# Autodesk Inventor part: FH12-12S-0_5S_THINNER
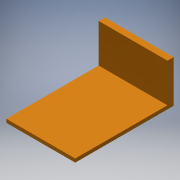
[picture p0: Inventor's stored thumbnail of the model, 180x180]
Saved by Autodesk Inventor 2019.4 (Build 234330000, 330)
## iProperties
Created: 2019-11
Part Number: FH12-12S-0_5S_THINNER
Material: Generic
Document SubType Name: Modeling
Designer: Willist
Density: 1 g/cm^3
Appearance: FH12-12S-0_5SH_THINER, FH12-12S-0_5S_THINNER
Author: Willist
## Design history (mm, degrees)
sketch "FH12-12S-0_5SH_THINER, FH12-12S-0_5S_THINNER_19"
  geometry: L1 (-5.6, 3.95)-(5.6, 3.95); L2 (5.6, 3.95)-(5.6, -2.9); L3 (5.6, -2.9)-(-5.6, -2.9); L4 (-5.6, -2.9)-(-5.6, 3.95)
  constraints: 8 end point
extrude "Extrusion1" join sketch "FH12-12S-0_5SH_THINER, FH12-12S-0_5S_THINNER_19" distance "d0" = 1; taper "d1" = 0 deg
sketch "Sketch2"
  geometry: L1 (-5.6, -2.9)-(5.6, -2.9) reference; L2 (-5.6, 3.95)-(-5.6, -2.9) reference; L3 (5.6, -2.9)-(-5.6, -2.9); L4 (-5.6, -2.9)-(-5.6, -2.329); L5 (-5.6, -2.329)-(5.6, -2.329); L6 (5.6, -2.329)-(5.6, -2.9); 1 further point
  constraints: 8 end point, 2 parallel, 1 horizontal, 1 perpendicular, 1 point on line
extrude "Extrusion2" join sketch "Sketch2" distance "d2" = 15; taper "d3" = 0 deg
body "Solid1"
